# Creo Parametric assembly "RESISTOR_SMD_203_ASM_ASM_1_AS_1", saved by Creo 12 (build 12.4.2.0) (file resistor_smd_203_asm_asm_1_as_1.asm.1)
Units: Custom; MM, KILOGRAM, SECS

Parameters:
  PTC_WM_ITERATION = "0"
  PTC_WM_VERSION = "-.0"
  PTC_WM_LIFECYCLE_STATE = "In Work"
  PTC_WM_LIFECYCLE = "MO_CADDocument"
  PTC_WM_CREATED_BY = "Maximilian Roepper (Z0017RMS: MO)"
  PTC_WM_CREATED_ON = "18-Sep-26 11:36:42 AM"
  PTC_WM_MODIFIED_BY = "Maximilian Roepper (Z0017RMS: MO)"
  PTC_WM_MODIFIED_ON = "18-Sep-26 11:36:46 AM"
  PDMLINKNUMBER = "PDM000071455143"
  PTC_WM_NUMBER = "PDM000071455143"

Other parameters: WEIGHT, WEIGHT_FACTOR, WEIGHT_ADD, MC_ERRORS, SUPPLIER

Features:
  1. coordinate system
  2. imported feature
  3. component "VALOR_PREDETERMINADO_PRT_1_PR_1"

Other named items: DRW_VIEW_ORG, ROUGH-GROB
